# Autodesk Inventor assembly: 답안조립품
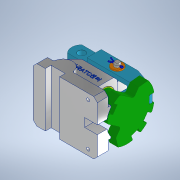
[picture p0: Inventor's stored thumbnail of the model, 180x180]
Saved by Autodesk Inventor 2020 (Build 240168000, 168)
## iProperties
Created: 2022-08
Part Number: 답안조립품
Document SubType Name: Assembly
Designer: com
Author: com
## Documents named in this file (8)
- C:\Users\com\Desktop\720806V1011\답안조립품.iam
- C:\Users\com\Desktop\720806V1011\본체.ipt
- C:\Users\com\Desktop\720806V1011\부시.ipt
- C:\Users\com\Desktop\720806V1011\분할축.ipt
- C:\Users\com\Desktop\720806V1011\분할대.ipt
- C:\Users\com\Desktop\720806V1011\와셔.ipt
- C:\Users\com\Desktop\720806V1011\클레비스핀.ipt
- C:\Users\com\Desktop\720806V1011\분할핀.ipt
